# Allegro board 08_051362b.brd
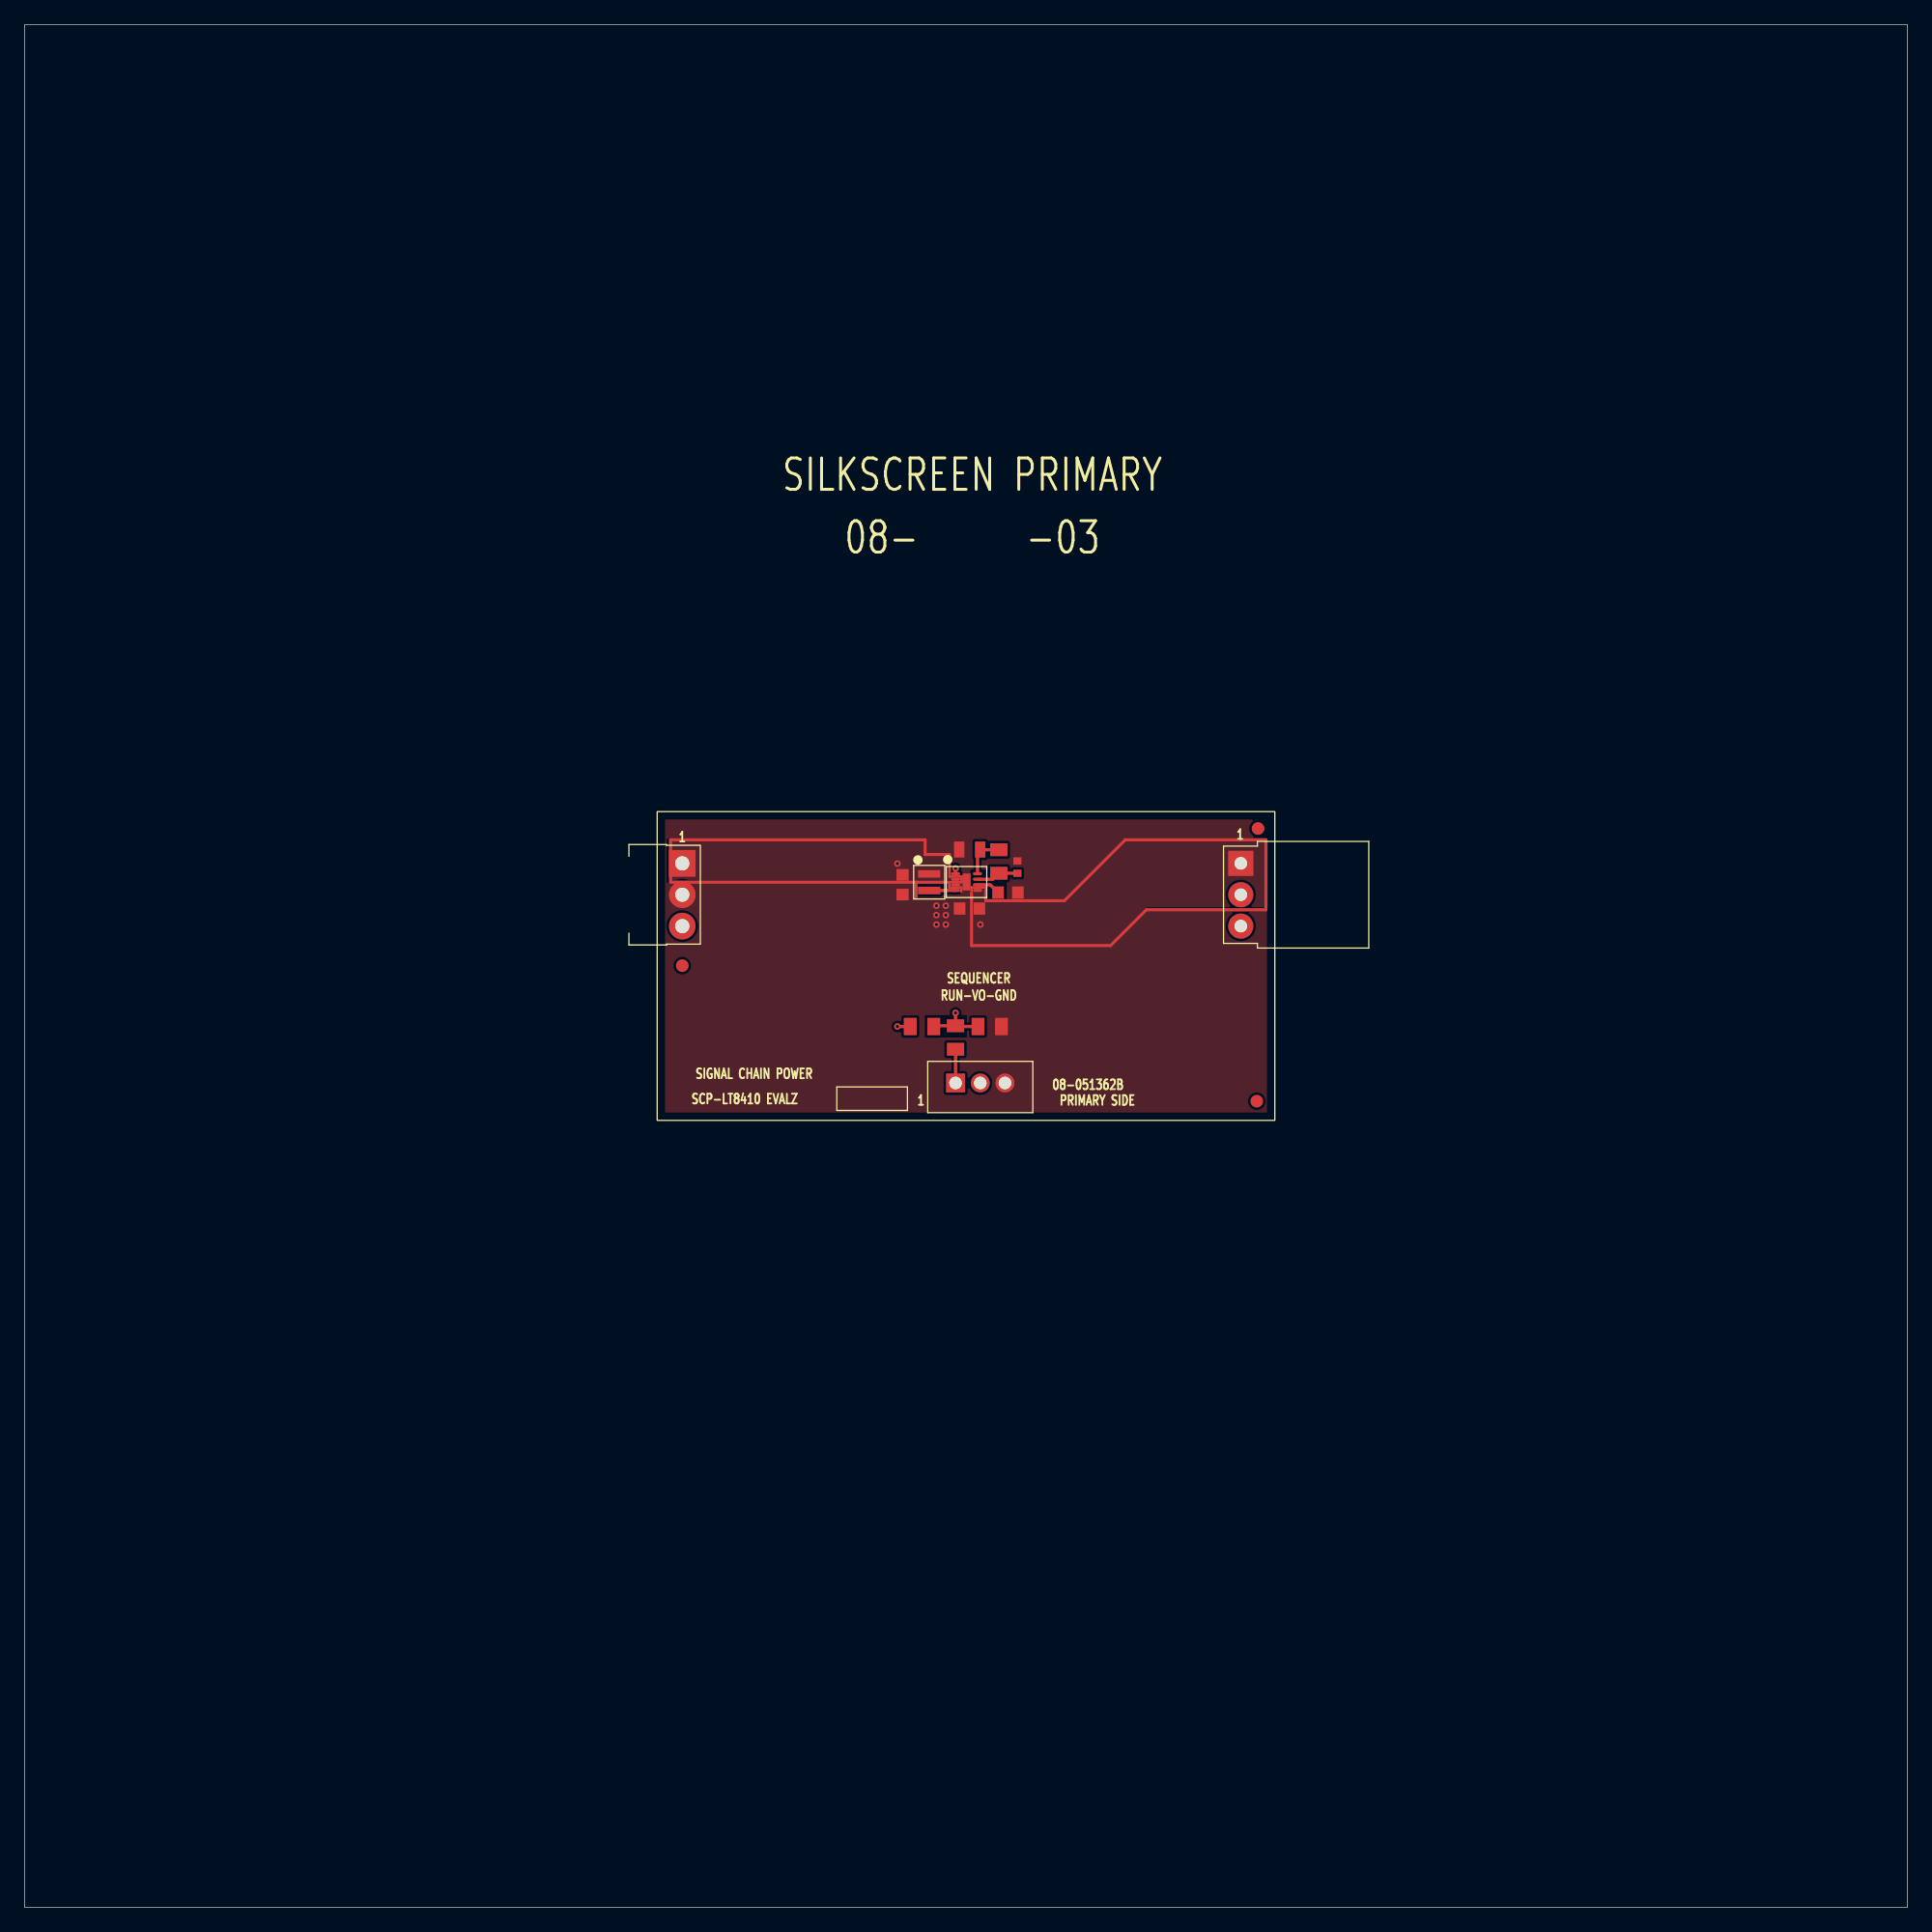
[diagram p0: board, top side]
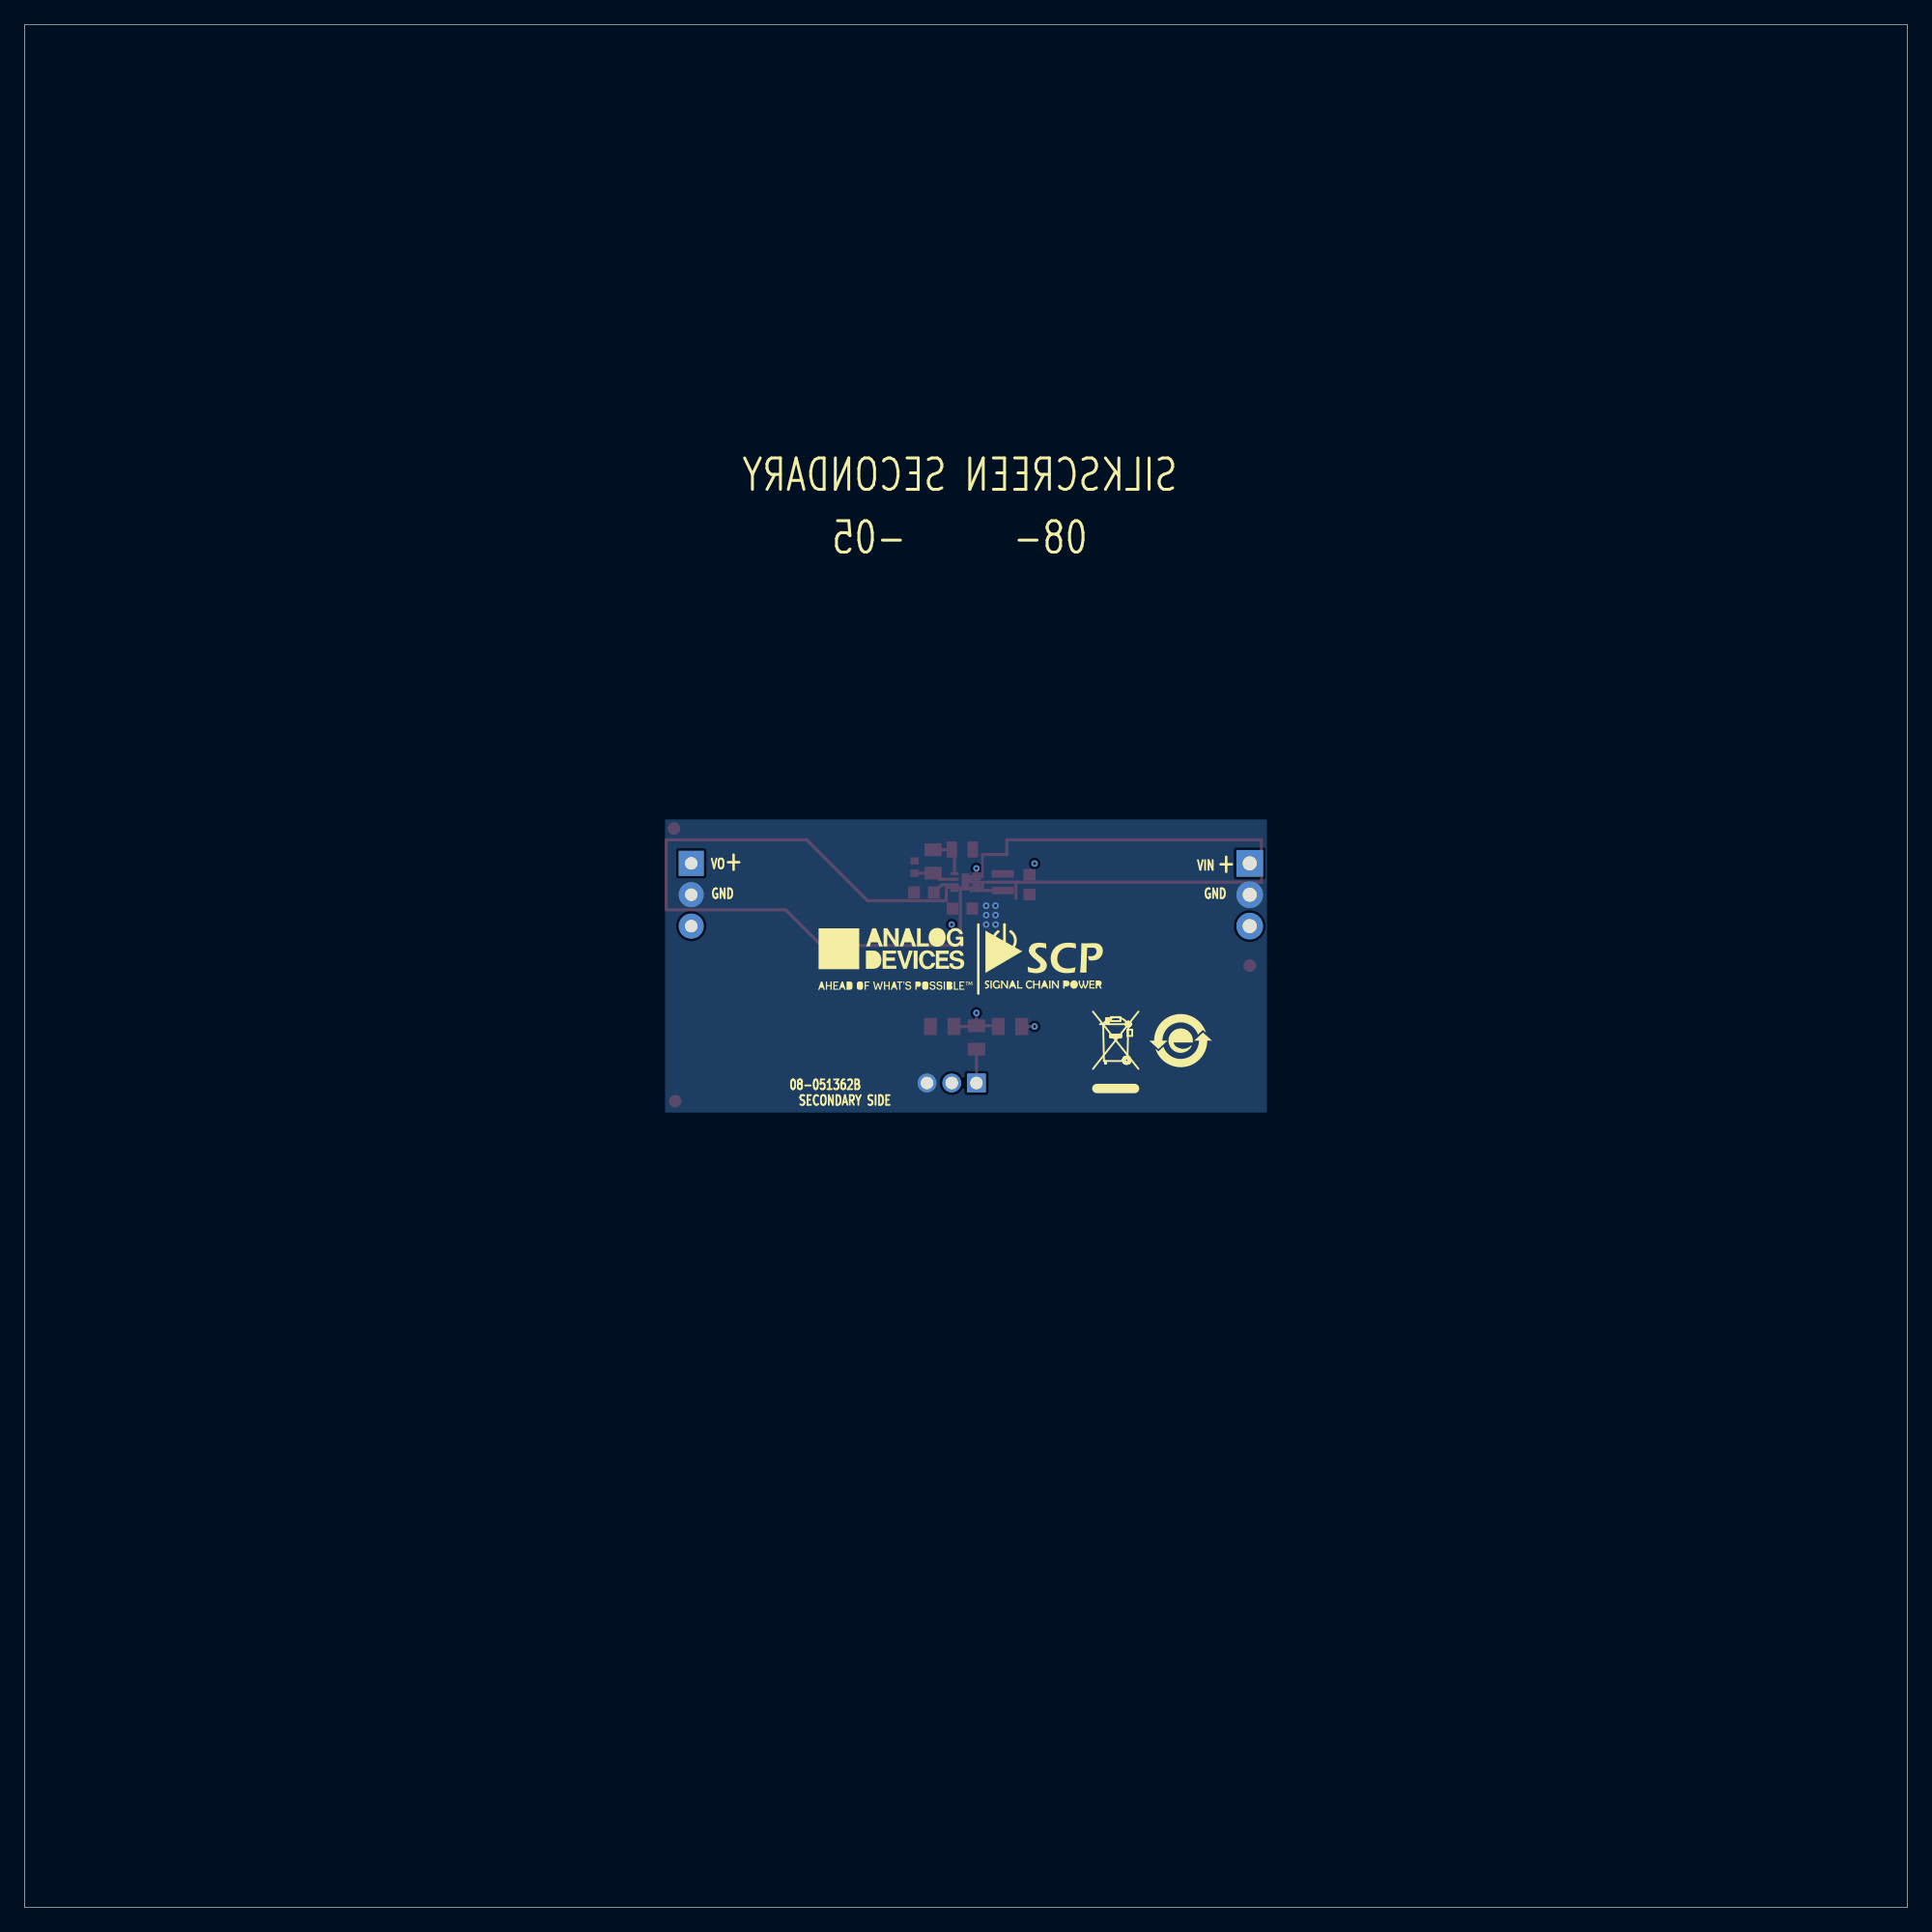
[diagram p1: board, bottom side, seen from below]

Outline 152.4 x 152.4 mm; copper layers: TOP, L2, L3, BOTTOM. Coordinates in mm from the lower left corner of the outline.
Outline path: 0,152.4 152.4,152.4 152.4,0 0,0 0,152.4

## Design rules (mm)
constraint set DEFAULT: min track width 0.203

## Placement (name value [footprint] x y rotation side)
C1  0.1UF  [C0603]  79.6 82.15 0 top
C2  2.2UF  [C0603]  71.06 82.78 270 top
C3  1UF  [C0603]  76.49 80.85 180 top
C4  0.1uF  [C0402]  80.36 84.2 90 top
INPUT  PBC03SBAN  [CNTHMHDRRA1X3L300W100H145]  53.23 84.51 270 top
L1  100UH  [LSML75W79H39_24X71]  73.22 82.99 270 top
NOREF  -  [unnamed]  99.74 65.26 0 top
NOREF#2  -  [#2]  101.19 63.71 90 top
NOREF#3  -  [#2]  -74.78 242.5 0 top
NOREF#4  -  [#2]  101.22 63.63 90 top
NOREF#5  -  [#2]  51.18 88.77 270 top
NOREF#6  -  [#2]  -146.92 -122.88 0 top
NOREF#7  -  [#2]  101.22 88.77 180 top
NOREF#8  -  [#2]  -298.45 -222.25 0 top
NOREF#9  -  [#2]  141.99 96.01 0 top
NOREF#10  -  [#2]  51.2 63.71 0 top
NOREF#11  -  [unnamed]  53.23 76.23 0 top
NOREF#12  -  [#2]  76.71 109.73 0 top
NOREF#13  -  [#2]  121.43 207.19 0 top
NOREF#14  -  [#2]  -84.59 14.53 0 top
NOREF#15  -  [#2]  51.18 63.63 0 top
NOREF#16  -  [unnamed]  99.84 87.33 0 top
NOREF#17  -  [#2]  -176.08 -131.37 0 top
NOREF#18  -  [#2]  69.87 77.02 180 bottom
NOREF#19  -  [#2]  58.82 70.16 180 bottom
NOREF#20  -  [#2]  64.28 65.97 180 bottom
NOREF#21  -  [#2]  82.22 76.74 180 bottom
OUTPUT  PPPC031LGBN-RC  [CNHDRRA1X3H108]  98.44 84.51 270 top
P1  53253-0370  [CNTHMHDR1X3L315W144H224]  75.36 66.73 0 top
R1  1MEG  [R0805]  72.64 71.3 0 top
R2  604K  [R0805]  78.86 84.66 90 top
R3  412K  [R0805#2]  76.5 85.63 180 top
R4  0  [R0805]  78.12 71.3 0 top
R5  100K  [R0805]  75.36 70.41 90 top
U1  LT8410EDC#PBF  [DFN8_2X2_PAD1_37X0_64]  76.24 83 270 top

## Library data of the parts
C1 = CAP: User Part Number: UPN; Tolerance: 10; alternate symbols: (); part number: CAP_SM-0.1UF,50V,10,E038267,C0603; tolerance: 10
C2 = CAP: User Part Number: UPN; Tolerance: 10; alternate symbols: (); part number: CAP_SM-2.2UF,25V,10,E031885,C0603; tolerance: 10
C3 = CAP: User Part Number: UPN; Tolerance: 10; alternate symbols: (); part number: CAP_SM-1UF,50V,10,E034224,C0603; tolerance: 10
C4 = CAP: User Part Number: UPN; Tolerance: 10; alternate symbols: (); part number: CAP_SM-0.1UF,16V,10,E018707,C0402; tolerance: 10
INPUT = CN3P: Tolerance: N/A; User Part Number: UPN; alternate symbols: (CNTHMHDRRA1X3L300W100H145_SCP); part number: CN3P_TH-PBC03SBAN,E034137,CNTHMHDRRA1X3L300W100H145; tolerance: N/A
L1 = IND: User Part Number: UPN; Tolerance: 20; alternate symbols: (); part number: IND_SM-100UH,20,E030141,LSML75W79H39_24X71; tolerance: 20
OUTPUT = CN3P: User Part Number: UPN; Tolerance: N/A; alternate symbols: (CNHDRRA1X3H108_SCP); part number: CN3P_TH-PPPC031LGBN-RC,E034111,CNHDRRA1X3H108; tolerance: N/A
P1 = CN3P: Tolerance: N/A; User Part Number: UPN; alternate symbols: (); part number: CN3P_TH-53253-0370,E033940,CNTHMHDR1X3L315W144H224; tolerance: N/A
R1 = RES: User Part Number: UPN; Tolerance: 5; alternate symbols: (); part number: RES_SM-1MEG,E033749,1/8W,5,R0805; tolerance: 5
R2 = RES: User Part Number: UPN; Tolerance: 1; alternate symbols: (); part number: RES_SM-604K,E033778,1/8W,1,R0805; tolerance: 1
R3 = RES: User Part Number: UPN; Tolerance: 1; alternate symbols: (R0805L); part number: RES_SM-412K,E004895,1/8W,1,R0805; tolerance: 1
R4 = RES: User Part Number: UPN; Tolerance: N/A; alternate symbols: (); part number: RES_SM-0,E030875,1/8W,N/A,R0805; tolerance: N/A
R5 = RES: User Part Number: UPN; Tolerance: 1; alternate symbols: (R0805L); part number: RES_SM-100K,E003488,1/8W,1,R0805; tolerance: 1
U1 = LINLT8410_X_SM-LT8410EDC#PBF,E033623,DFN8_2X2_PAD1_37X0_64-DFN8_2X2_PAD1_37X0_64: User Part Number: UPN; Tolerance: N/A

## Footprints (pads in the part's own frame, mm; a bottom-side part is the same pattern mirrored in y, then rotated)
C0402
  rect 0.584x0.66 smd: 1(-0.5,0) 2(0.5,0)
C0603
  rect 0.94x0.991 smd: 1(-0.8,0) 2(0.8,0)
CNHDRRA1X3H108
  rect 2.032x2.032 hole 1.016: 1(0,0)
  round 2.032 hole 1.016: 2(2.54,0) 3(5.08,0)
CNTHMHDR1X3L315W144H224
  rect 1.524x1.524 hole 1.016: 1(0,0)
  round 1.524 hole 1.016: 2(2,0) 3(4,0)
CNTHMHDRRA1X3L300W100H145
  rect 2.159x2.159 hole 1.143: 1(0,0)
  round 2.159 hole 1.143: 2(2.54,0) 3(5.08,0)
DFN8_2X2_PAD1_37X0_64
  oval 0.254x0.737 smd: 1(-0.675,-0.888) 2(-0.225,-0.888) 3(0.225,-0.888) 4(0.675,-0.888) 5(0.675,0.888) 6(0.225,0.888) 7(-0.225,0.888) 8(-0.675,0.888)
  rect 1.372x0.635 smd: PAD(0,0)
LSML75W79H39_24X71
  rect 0.61x1.803 smd: 1(-0.673,0) 2(0.673,0)
R0805
  rect 1.041x1.397 smd: 1(-0.95,0) 2(0.95,0)
R0805#2
  rect 0.838x1.295 smd: 1(-0.85,0) 2(0.85,0)
unnamed
  round 1.016 smd: (0,0)

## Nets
GND: C1.2(N2) C2.2(N2) C3.2(N2) C4.2(N2) INPUT.2 OUTPUT.2 P1.3(N3) R3.2(N2) R4.2(N2) U1.3 U1.PAD
UNNAMED_2_CAP_I12_N1: C2.1 INPUT.1 L1.1 R1.1 U1.2
UNNAMED_2_CAP_I17_N1: C4.1 R2.1 U1.7(VREF)
UNNAMED_2_CAP_I19_N1: C1.1 U1.6
UNNAMED_2_CN3P_I1_N1: P1.1 R5.1
UNNAMED_2_IND_I13_N2: L1.2(N2) U1.4
UNNAMED_2_LINLT8410X_I23_FBP: R2.2(N2) R3.1 U1.8
UNNAMED_2_LINLT8410X_I23_SHDNN: R1.2(N2) R4.1 R5.2(N2) U1.1
VO+: C3.1 OUTPUT.1 P1.2 U1.5

Pads without a net: INPUT 3; OUTPUT 3

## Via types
v1: diameter 0.533, hole 0.254, TOP to BOTTOM, 11 vias

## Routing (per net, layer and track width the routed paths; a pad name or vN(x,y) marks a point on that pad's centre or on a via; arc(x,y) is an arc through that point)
GND: length 0
  BOTTOM w0: 66.27,76.9 66.27,76.9
  vias: v1(73.81,81.08) v1(73.81,80.32) v1(73.81,79.56) v1(74.57,81.08) v1(74.57,80.32) v1(74.57,79.56)
UNNAMED_2_CAP_I12_N1: length 14.2
  TOP w0.254: R1.1 v1(70.65,71.3)
  L3 w0.254: v1(70.65,71.3) v1(70.65,84.49)
UNNAMED_2_CAP_I17_N1: length 3.4
  TOP w0.254: U1.7 78.37,83.22 R2.1 80.35,83.71 C4.1
UNNAMED_2_CAP_I19_N1: length 1.9
  TOP w0.254: U1.6 78.16,82.77 C1.1
UNNAMED_2_CN3P_I1_N1: length 2.7
  TOP w0.254: R5.1 P1.1
UNNAMED_2_IND_I13_N2: length 2.1
  TOP w0.254: L1.2 74.45,82.31 74.45,82.32 U1.4
UNNAMED_2_LINLT8410X_I23_FBP: length 3.6
  TOP w0.254: R2.2 77.36,85.61 R3.1 77.13,85.41 U1.8
UNNAMED_2_LINLT8410X_I23_SHDNN: length 16.8
  TOP w0.254: v1(75.36,72.4) R5.2 ; R5.2 75.42,71.3 R4.1 ; R5.2 73.65,71.36 R1.2 ; U1.1 v1(75.36,84.1)
  L3 w0.254: v1(75.36,84.1) v1(75.36,72.4)
VO+: length 12.8
  L3 w0.254: P1.2 v1(77.36,79.56)

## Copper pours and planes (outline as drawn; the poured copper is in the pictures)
GND on TOP: 51.84,88.06 100.56,88.06 100.56,86.54 89.04,86.54 84.12,81.61 79.5,81.61 79.5,84 76.55,84 76.55,82.15 76.52,82.12 76.52,77.73 87.96,77.73 90.85,80.62 100.56,80.62 100.56,64.34 51.84,64.34 ; 2 cut-outs
GND on BOTTOM, L3: 51.84,88.06 100.56,88.06 100.56,64.34 51.84,64.34 ; 1 cut-out
GND on L2: 51.84,88.06 100.56,88.06 100.56,86.54 89.07,86.54 84.14,81.61 75.1,81.61 75.03,81.54 75.03,81.43 75.1,81.36 84.25,81.36 89.17,86.29 100.35,86.29 100.35,80.9 90.72,80.9 87.83,78.01 76.78,78.01 76.78,80.11 75.3,80.11 75.23,80.04 75.23,79.94 75.3,79.86 76.52,79.86 76.52,77.75 87.93,77.75 90.83,80.65 100.56,80.65 100.56,64.34 51.84,64.34
UNNAMED_2_CAP_I12_N1 on TOP: 52.17,86.29 72.76,86.29 72.76,85.09 74.77,85.09 74.77,83.34 75.74,83.34 75.74,83.09 74.52,83.09 74.47,83.14 52.17,83.14
VO+ on TOP: 89.15,86.29 100.35,86.29 100.35,80.95 90.82,80.95 87.85,77.98 76.78,77.98 76.78,82.12 76.75,82.15 76.75,82.45 77.69,82.45 77.69,82.4 77.67,82.38 77.67,81.36 84.22,81.36

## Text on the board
Ref Des/Silkscreen Bottom: GND | VIN | SECONDARY SIDE | 08-051362B | VO | +
User.Comments: 4.    RoHS COMPLIANCE: ASSEMBLY VENDOR SHOULD ASSURE COMPLIANCE | WITH LEAD-FREE AND RoHS PCB ASSEMBLY STANDARDS (EU RoHS | DIRECTIVE 2002/95/EC).
Ref Des/Silkscreen Top: SCP-LT8410 EVALZ | SIGNAL CHAIN POWER | SEQUENCER | RUN-VO-GND | 08-051362B | PRIMARY SIDE
PAGE_OUTLINE: B | AS PER ECR-086559 | 06MAY19 | J VIERNES
DIMENSION: REF | -0.819 | 0.165 | "0" | SEE FAB NOTE 15 | DIA MAX | -0.80 | 1.889
User.15: ROHS COMPLIANCE NOTE: | ENIG (Electroless Nickel/Immersion Gold) | PER IPC-4552 LATEST REVISION | HOMOGENOUS MATERIALS IN THIS BOARD SHALL BE COMPLIANT | THE EU RoHS DIRECTIVE 2002/95/EC | 15.    THRU VIAS TO BE FILLED WITH SOLDERMASK. | 0.035"
User.17: L2 | L2 AGND | 08-      -07
User.18: L3 | 08-      -08
User.45: FIGURE | SIZE | 10.0 | 40.0 | 45.0 | PLATED | FINISHED HOLES IN MILS | ALL UNITS ARE IN MILS | QTY | 11 | 6 | 3 | TOLERANCE/NOTES
